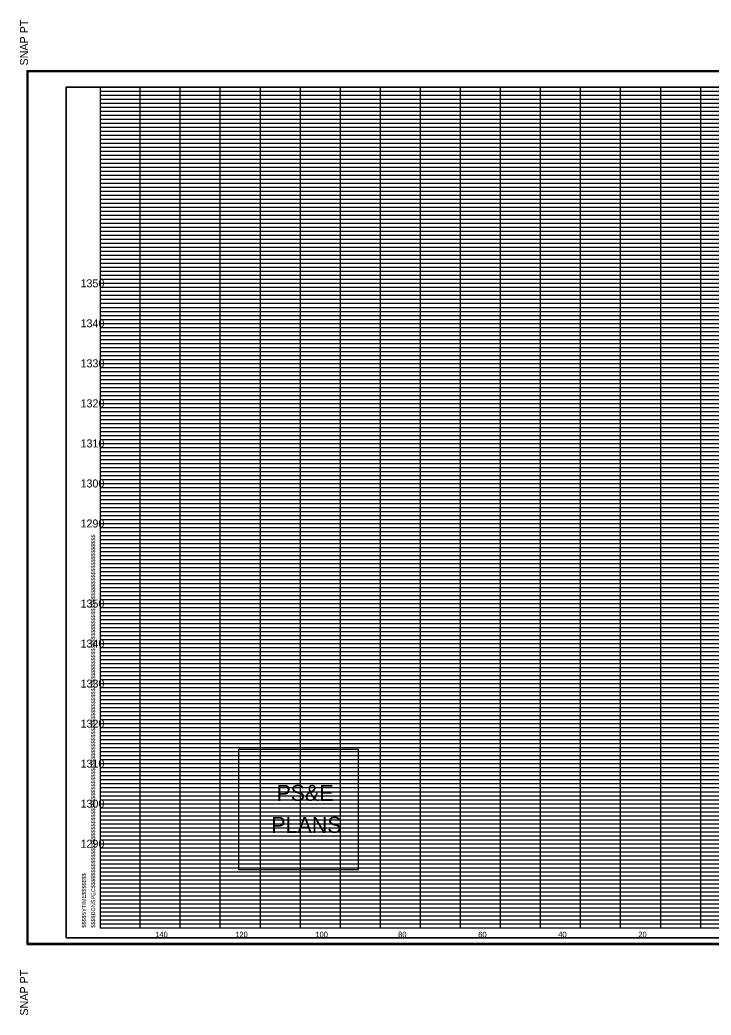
# Model space of a CAD drawing. Extents: x 980 to 1324, y 978 to 2847.
# Drawn here: x 979.9 to 1152.6, y 2058.2 to 2306.8 of the extents above; entities that cross this region are included whole.
import ezdxf

# ---------------------------------------------------------------- set-up
doc = ezdxf.new("R2010")
doc.units = 0
for name, color, linetype in [('DESIGN - SHEET - Corner Text', 7, 'Continuous'), ('DESIGN - SHEET - Light Grid', 7, 'Continuous'), ('DESIGN - SHEET - Linework', 7, 'Continuous'), ('DESIGN - SHEET - Plot Shape', 7, 'Continuous'), ('DESIGN - TYPICAL - Text', 7, 'Continuous')]:
    doc.layers.add(name, color=color, linetype=linetype)

# ---------------------------------------------------------------- blocks, each defined once
blk = doc.blocks.new('XSTSHT')
at = {"layer": 'DESIGN - SHEET - Light Grid'}
for p, q in [((0, 20.9), (8, 20.9)), ((8, 20.9), (16, 20.9)), ((0, 20.8), (8, 20.8)), ((0, 20.7), (8, 20.7)), ((8, 20.8), (16, 20.8)), ((8, 20.7), (16, 20.7)), ((0, 20.6), (8, 20.6)), ((0, 20.5), (8, 20.5)), ((0, 20.4), (8, 20.4)), ((8, 20.6), (16, 20.6)), ((8, 20.5), (16, 20.5)), ((8, 20.4), (16, 20.4)), ((0, 20.3), (8, 20.3)), ((0, 20.2), (8, 20.2)), ((8, 20.3), (16, 20.3)), ((8, 20.2), (16, 20.2)), ((0, 20.1), (8, 20.1)), ((0, 19.9), (8, 19.9)), ((8, 20.1), (16, 20.1)), ((8, 19.9), (16, 19.9)), ((0, 19.8), (8, 19.8)), ((0, 19.7), (8, 19.7)), ((8, 19.8), (16, 19.8)), ((8, 19.7), (16, 19.7)), ((0, 19.6), (8, 19.6)), ((0, 19.5), (8, 19.5)), ((0, 19.4), (8, 19.4)), ((8, 19.6), (16, 19.6)), ((8, 19.5), (16, 19.5)), ((8, 19.4), (16, 19.4)), ((0, 19.3), (8, 19.3)), ((0, 19.2), (8, 19.2)), ((8, 19.3), (16, 19.3)), ((8, 19.2), (16, 19.2)), ((0, 19.1), (8, 19.1)), ((0, 18.9), (8, 18.9)), ((8, 19.1), (16, 19.1)), ((8, 18.9), (16, 18.9)), ((0, 18.8), (8, 18.8)), ((0, 18.7), (8, 18.7)), ((8, 18.8), (16, 18.8)), ((8, 18.7), (16, 18.7)), ((0, 18.6), (8, 18.6)), ((0, 18.5), (8, 18.5)), ((0, 18.4), (8, 18.4)), ((8, 18.6), (16, 18.6)), ((8, 18.5), (16, 18.5)), ((8, 18.4), (16, 18.4)), ((0, 18.3), (8, 18.3)), ((0, 18.2), (8, 18.2)), ((8, 18.3), (16, 18.3)), ((8, 18.2), (16, 18.2)), ((0, 18.1), (8, 18.1)), ((8, 18.1), (16, 18.1)), ((0, 17.9), (8, 17.9)), ((0, 17.8), (8, 17.8)), ((0, 17.7), (8, 17.7)), ((8, 17.9), (16, 17.9)), ((8, 17.8), (16, 17.8)), ((8, 17.7), (16, 17.7)), ((0, 17.6), (8, 17.6)), ((0, 17.5), (8, 17.5)), ((8, 17.6), (16, 17.6)), ((8, 17.5), (16, 17.5)), ((0, 17.4), (8, 17.4)), ((0, 17.3), (8, 17.3)), ((0, 17.2), (8, 17.2)), ((8, 17.4), (16, 17.4)), ((8, 17.3), (16, 17.3)), ((8, 17.2), (16, 17.2)), ((0, 17.1), (8, 17.1)), ((8, 17.1), (16, 17.1)), ((0, 16.9), (8, 16.9)), ((0, 16.8), (8, 16.8)), ((0, 16.7), (8, 16.7)), ((8, 16.9), (16, 16.9)), ((8, 16.8), (16, 16.8)), ((8, 16.7), (16, 16.7)), ((0, 16.6), (8, 16.6)), ((0, 16.5), (8, 16.5)), ((8, 16.6), (16, 16.6)), ((8, 16.5), (16, 16.5)), ((0, 16.4), (8, 16.4)), ((0, 16.3), (8, 16.3)), ((0, 16.2), (8, 16.2)), ((8, 16.4), (16, 16.4)), ((8, 16.3), (16, 16.3)), ((8, 16.2), (16, 16.2)), ((0, 16.1), (8, 16.1)), ((8, 16.1), (16, 16.1)), ((0, 15.9), (8, 15.9)), ((0, 15.8), (8, 15.8)), ((0, 15.7), (8, 15.7)), ((8, 15.9), (16, 15.9)), ((8, 15.8), (16, 15.8)), ((8, 15.7), (16, 15.7)), ((0, 15.6), (8, 15.6)), ((0, 15.5), (8, 15.5)), ((8, 15.6), (16, 15.6)), ((8, 15.5), (16, 15.5)), ((0, 15.4), (8, 15.4)), ((0, 15.3), (8, 15.3)), ((0, 15.2), (8, 15.2)), ((8, 15.4), (16, 15.4)), ((8, 15.3), (16, 15.3)), ((8, 15.2), (16, 15.2)), ((0, 15.1), (8, 15.1)), ((8, 15.1), (16, 15.1)), ((0, 14.9), (8, 14.9)), ((0, 14.8), (8, 14.8)), ((0, 14.7), (8, 14.7)), ((8, 14.9), (16, 14.9)), ((8, 14.8), (16, 14.8)), ((8, 14.7), (16, 14.7)), ((0, 14.6), (8, 14.6)), ((0, 14.5), (8, 14.5)), ((8, 14.6), (16, 14.6)), ((8, 14.5), (16, 14.5)), ((0, 14.4), (8, 14.4)), ((0, 14.3), (8, 14.3)), ((0, 14.2), (8, 14.2)), ((8, 14.4), (16, 14.4)), ((8, 14.3), (16, 14.3)), ((8, 14.2), (16, 14.2)), ((0, 14.1), (8, 14.1)), ((8, 14.1), (16, 14.1)), ((0, 13.9), (8, 13.9)), ((0, 13.8), (8, 13.8)), ((0, 13.7), (8, 13.7)), ((8, 13.9), (16, 13.9)), ((8, 13.8), (16, 13.8)), ((8, 13.7), (16, 13.7)), ((0, 13.6), (8, 13.6)), ((0, 13.5), (8, 13.5)), ((8, 13.6), (16, 13.6)), ((8, 13.5), (16, 13.5)), ((0, 13.4), (8, 13.4)), ((0, 13.3), (8, 13.3)), ((0, 13.2), (8, 13.2)), ((8, 13.4), (16, 13.4)), ((8, 13.3), (16, 13.3)), ((8, 13.2), (16, 13.2)), ((0, 13.1), (8, 13.1)), ((8, 13.1), (16, 13.1)), ((0, 12.9), (8, 12.9)), ((0, 12.8), (8, 12.8)), ((0, 12.7), (8, 12.7)), ((8, 12.9), (16, 12.9)), ((8, 12.8), (16, 12.8)), ((8, 12.7), (16, 12.7)), ((0, 12.6), (8, 12.6)), ((0, 12.5), (8, 12.5)), ((8, 12.6), (16, 12.6)), ((8, 12.5), (16, 12.5)), ((0, 12.4), (8, 12.4)), ((0, 12.3), (8, 12.3)), ((0, 12.2), (8, 12.2)), ((8, 12.4), (16, 12.4)), ((8, 12.3), (16, 12.3)), ((8, 12.2), (16, 12.2)), ((0, 12.1), (8, 12.1)), ((8, 12.1), (16, 12.1)), ((0, 11.9), (8, 11.9)), ((0, 11.8), (8, 11.8)), ((0, 11.7), (8, 11.7)), ((8, 11.9), (16, 11.9)), ((8, 11.8), (16, 11.8)), ((8, 11.7), (16, 11.7)), ((0, 11.6), (8, 11.6)), ((0, 11.5), (8, 11.5)), ((8, 11.6), (16, 11.6)), ((8, 11.5), (16, 11.5)), ((0, 11.4), (8, 11.4)), ((0, 11.3), (8, 11.3)), ((0, 11.2), (8, 11.2)), ((8, 11.4), (16, 11.4)), ((8, 11.3), (16, 11.3)), ((8, 11.2), (16, 11.2)), ((0, 11.1), (8, 11.1)), ((8, 11.1), (16, 11.1)), ((0, 10.9), (8, 10.9)), ((0, 10.8), (8, 10.8)), ((0, 10.7), (8, 10.7)), ((8, 10.9), (16, 10.9)), ((8, 10.8), (16, 10.8)), ((8, 10.7), (16, 10.7)), ((0, 10.6), (8, 10.6)), ((0, 10.5), (8, 10.5)), ((8, 10.6), (16, 10.6)), ((8, 10.5), (16, 10.5)), ((0, 10.4), (8, 10.4)), ((0, 10.3), (8, 10.3)), ((0, 10.2), (8, 10.2)), ((8, 10.4), (16, 10.4)), ((8, 10.3), (16, 10.3)), ((8, 10.2), (16, 10.2)), ((0, 10.1), (8, 10.1)), ((8, 10.1), (16, 10.1)), ((0, 9.9), (8, 9.9)), ((0, 9.8), (8, 9.8)), ((0, 9.7), (8, 9.7)), ((8, 9.9), (16, 9.9)), ((8, 9.8), (16, 9.8)), ((8, 9.7), (16, 9.7)), ((0, 9.6), (8, 9.6)), ((0, 9.5), (8, 9.5)), ((8, 9.6), (16, 9.6)), ((8, 9.5), (16, 9.5)), ((0, 9.4), (8, 9.4)), ((0, 9.3), (8, 9.3)), ((0, 9.2), (8, 9.2)), ((8, 9.4), (16, 9.4)), ((8, 9.3), (16, 9.3)), ((8, 9.2), (16, 9.2)), ((0, 9.1), (8, 9.1)), ((8, 9.1), (16, 9.1)), ((0, 8.9), (8, 8.9)), ((0, 8.8), (8, 8.8)), ((8, 8.9), (16, 8.9)), ((8, 8.8), (16, 8.8)), ((0, 8.7), (8, 8.7)), ((0, 8.6), (8, 8.6)), ((0, 8.5), (8, 8.5)), ((8, 8.7), (16, 8.7)), ((8, 8.6), (16, 8.6)), ((8, 8.5), (16, 8.5)), ((0, 8.4), (8, 8.4)), ((0, 8.3), (8, 8.3)), ((8, 8.4), (16, 8.4)), ((8, 8.3), (16, 8.3)), ((0, 8.2), (8, 8.2)), ((0, 8.1), (8, 8.1)), ((8, 8.2), (16, 8.2)), ((8, 8.1), (16, 8.1)), ((0, 7.9), (8, 7.9)), ((0, 7.8), (8, 7.8)), ((8, 7.9), (16, 7.9)), ((8, 7.8), (16, 7.8)), ((0, 7.7), (8, 7.7)), ((0, 7.6), (8, 7.6)), ((0, 7.5), (8, 7.5)), ((8, 7.7), (16, 7.7)), ((8, 7.6), (16, 7.6)), ((8, 7.5), (16, 7.5)), ((0, 7.4), (8, 7.4)), ((0, 7.3), (8, 7.3)), ((8, 7.4), (16, 7.4)), ((8, 7.3), (16, 7.3)), ((0, 7.2), (8, 7.2)), ((0, 7.1), (8, 7.1)), ((8, 7.2), (16, 7.2)), ((8, 7.1), (16, 7.1)), ((0, 6.9), (8, 6.9)), ((0, 6.8), (8, 6.8)), ((8, 6.9), (16, 6.9)), ((8, 6.8), (16, 6.8)), ((0, 6.7), (8, 6.7)), ((0, 6.6), (8, 6.6)), ((0, 6.5), (8, 6.5)), ((8, 6.7), (16, 6.7)), ((8, 6.6), (16, 6.6)), ((8, 6.5), (16, 6.5)), ((0, 6.4), (8, 6.4)), ((0, 6.3), (8, 6.3)), ((8, 6.4), (16, 6.4)), ((8, 6.3), (16, 6.3)), ((0, 6.2), (8, 6.2)), ((0, 6.1), (8, 6.1)), ((8, 6.2), (16, 6.2)), ((8, 6.1), (16, 6.1)), ((0, 5.9), (8, 5.9)), ((0, 5.8), (8, 5.8)), ((8, 5.9), (16, 5.9)), ((8, 5.8), (16, 5.8)), ((0, 5.7), (8, 5.7)), ((0, 5.6), (8, 5.6)), ((0, 5.5), (8, 5.5)), ((8, 5.7), (16, 5.7)), ((8, 5.6), (16, 5.6)), ((8, 5.5), (16, 5.5)), ((0, 5.4), (8, 5.4)), ((0, 5.3), (8, 5.3)), ((8, 5.4), (16, 5.4)), ((8, 5.3), (16, 5.3)), ((0, 5.2), (8, 5.2)), ((0, 5.1), (8, 5.1)), ((8, 5.2), (16, 5.2)), ((8, 5.1), (16, 5.1)), ((0, 4.9), (8, 4.9)), ((0, 4.8), (8, 4.8)), ((8, 4.9), (16, 4.9)), ((8, 4.8), (16, 4.8)), ((0, 4.7), (8, 4.7)), ((0, 4.6), (8, 4.6)), ((0, 4.5), (8, 4.5)), ((8, 4.7), (16, 4.7)), ((8, 4.6), (16, 4.6)), ((8, 4.5), (16, 4.5)), ((0, 4.4), (8, 4.4)), ((0, 4.3), (8, 4.3)), ((8, 4.4), (16, 4.4)), ((8, 4.3), (16, 4.3)), ((0, 4.2), (8, 4.2)), ((0, 4.1), (8, 4.1)), ((8, 4.2), (16, 4.2)), ((8, 4.1), (16, 4.1)), ((0, 3.9), (8, 3.9)), ((0, 3.8), (8, 3.8)), ((8, 3.9), (16, 3.9)), ((8, 3.8), (16, 3.8)), ((0, 3.7), (8, 3.7)), ((0, 3.6), (8, 3.6)), ((0, 3.5), (8, 3.5)), ((8, 3.7), (16, 3.7)), ((8, 3.6), (16, 3.6)), ((8, 3.5), (16, 3.5)), ((0, 3.4), (8, 3.4)), ((0, 3.3), (8, 3.3)), ((8, 3.4), (16, 3.4)), ((8, 3.3), (16, 3.3)), ((0, 3.2), (8, 3.2)), ((0, 3.1), (8, 3.1)), ((8, 3.2), (16, 3.2)), ((8, 3.1), (16, 3.1)), ((0, 2.9), (8, 2.9)), ((0, 2.8), (8, 2.8)), ((8, 2.9), (16, 2.9)), ((8, 2.8), (16, 2.8)), ((0, 2.7), (8, 2.7)), ((0, 2.6), (8, 2.6)), ((0, 2.5), (8, 2.5)), ((8, 2.7), (16, 2.7)), ((8, 2.6), (16, 2.6)), ((8, 2.5), (16, 2.5)), ((0, 2.4), (8, 2.4)), ((0, 2.3), (8, 2.3)), ((8, 2.4), (16, 2.4)), ((8, 2.3), (16, 2.3)), ((0, 2.2), (8, 2.2)), ((0, 2.1), (8, 2.1)), ((8, 2.2), (16, 2.2)), ((8, 2.1), (16, 2.1)), ((0, 1.9), (8, 1.9)), ((0, 1.8), (8, 1.8)), ((8, 1.9), (16, 1.9)), ((8, 1.8), (16, 1.8)), ((0, 1.7), (8, 1.7)), ((0, 1.6), (8, 1.6)), ((0, 1.5), (8, 1.5)), ((8, 1.7), (16, 1.7)), ((8, 1.6), (16, 1.6)), ((8, 1.5), (16, 1.5)), ((0, 1.4), (8, 1.4)), ((0, 1.3), (8, 1.3)), ((8, 1.4), (16, 1.4)), ((8, 1.3), (16, 1.3)), ((0, 1.2), (8, 1.2)), ((0, 1.1), (8, 1.1)), ((8, 1.2), (16, 1.2)), ((8, 1.1), (16, 1.1)), ((0, 0.9), (8, 0.9)), ((0, 0.8), (8, 0.8)), ((8, 0.9), (16, 0.9)), ((8, 0.8), (16, 0.8)), ((0, 0.7), (8, 0.7)), ((0, 0.6), (8, 0.6)), ((0, 0.5), (8, 0.5)), ((8, 0.7), (16, 0.7)), ((8, 0.6), (16, 0.6)), ((8, 0.5), (16, 0.5)), ((0, 0.4), (8, 0.4)), ((0, 0.3), (8, 0.3)), ((8, 0.4), (16, 0.4)), ((8, 0.3), (16, 0.3)), ((0, 0.2), (8, 0.2)), ((0, 0.1), (8, 0.1)), ((8, 0.2), (16, 0.2)), ((8, 0.1), (16, 0.1))]:
    blk.add_line(p, q, dxfattribs=at)
at = {"layer": 'DESIGN - SHEET - Linework'}
for p, q in [((-1.823, -0.414), (-1.823, 21.414)), ((-1.823, 21.414), (32.217, 21.414)), ((1, 0), (1, 21)), ((2, 0), (2, 21)), ((3, 0), (3, 21)), ((4, 0), (4, 21)), ((5, 0), (5, 21)), ((6, 0), (6, 21)), ((7, 0), (7, 21)), ((8, 0), (8, 21)), ((9, 0), (9, 21)), ((10, 0), (10, 21)), ((11, 0), (11, 21)), ((12, 0), (12, 21)), ((13, 0), (13, 21)), ((14, 0), (14, 21)), ((15, 0), (15, 21)), ((0, 20), (28, 20)), ((0, 19), (32, 19)), ((0, 18), (32, 18)), ((0, 17), (32, 17)), ((0, 16), (32, 16)), ((0, 15), (32, 15)), ((0, 14), (32, 14)), ((0, 13), (32, 13)), ((0, 12), (32, 12)), ((0, 11), (32, 11)), ((0, 10), (32, 10)), ((0, 9), (32, 9)), ((0, 8), (32, 8)), ((0, 7), (32, 7)), ((0, 6), (32, 6)), ((0, 5), (32, 5)), ((0, 4), (32, 4)), ((0, 3), (32, 3)), ((0, 2), (32, 2)), ((0, 1), (32, 1)), ((-1.823, -0.414), (32.217, -0.414))]:
    blk.add_line(p, q, dxfattribs=at)
blk.add_lwpolyline([(0, 21), (0, 0), (32, 0), (32, 21), (0, 21)], dxfattribs=at)
at = {"layer": 'DESIGN - SHEET - Plot Shape'}
for points in [[(-1.803, 21.394), (32.197, 21.394), (32.197, -0.394), (-1.803, -0.394)], [(-0.85, 21), (32, 21), (32, -0.25), (-0.85, -0.25)]]:
    blk.add_lwpolyline(points, close=True, dxfattribs=at)
at = {"layer": 'DESIGN - SHEET - Corner Text'}
for s, height, p in [('  SNAP PT', 0.2, (-1.803, 21.394)), ('$$$$DGNSPEC$$$$$$$$$$$$$$$$$$$$$$$$$$$$$$$$$$$$$$$$$$$$$$$$$$$$$$$$$$$$$$$$$$$$$$$$$$$$$$$$$$$$$$$$$$$$$$$$$$$$$$$$$$$$$$$$$$$', 0.100002, (-0.126, 0)), ('$$$$SYTIME$$$$$$$', 0.1, (-0.358, 0)), ('SNAP PT  ', 0.2, (-1.803, -2.194))]:
    blk.add_text(s, height=height, rotation=90, dxfattribs=at).set_placement(p)

msp = doc.modelspace()

# ---------------------------------------------------------------- linework, layer by layer
at = {"layer": 'DESIGN - SHEET - Corner Text'}
msp.add_lwpolyline([(1034.51, 2124.53), (1034.51, 2094.53), (1064.51, 2094.53), (1064.51, 2124.53)], close=True, dxfattribs=at)
at = {"layer": 'DESIGN - SHEET - Plot Shape'}
msp.add_lwpolyline([(991.5, 2077.5), (1320, 2077.5), (1320, 2290), (991.5, 2290)], close=True, dxfattribs=at)

# ---------------------------------------------------------------- block references
at = {"layer": 'DESIGN - SHEET - Plot Shape', "xscale": 10, "yscale": 10}
msp.add_blockref('XSTSHT', (1000, 2080), dxfattribs=at)

# ---------------------------------------------------------------- texts
at = {"layer": 'DESIGN - SHEET - Corner Text'}
for s, p in [('PS&E', (1044.02, 2111.7)), ('PLANS', (1042.74, 2103.7))]:
    msp.add_text(s, height=4, dxfattribs=at).set_placement(p)
at = {"layer": 'DESIGN - TYPICAL - Text'}
for s, height, p in [('     1350     ', 2, (991.37, 2240)), ('     1340     ', 2, (991.37, 2230)), ('     1330     ', 2, (991.37, 2220)), ('     1320     ', 2, (991.37, 2210)), ('     1310     ', 2, (991.37, 2200)), ('     1300     ', 2, (991.37, 2190)), ('     1290     ', 2, (991.37, 2180)), ('     1350     ', 2, (991.37, 2160)), ('     1340     ', 2, (991.37, 2150)), ('     1330     ', 2, (991.37, 2140)), ('     1320     ', 2, (991.37, 2130)), ('     1310     ', 2, (991.37, 2120)), ('     1300     ', 2, (991.37, 2110)), ('     1290     ', 2, (991.37, 2100)), ('     140     ', 1.4, (1011.14, 2077.6)), ('     120     ', 1.4, (1031.14, 2077.6)), ('     100     ', 1.4, (1051.14, 2077.6)), ('     80     ', 1.4, (1071.82, 2077.6)), ('     60     ', 1.4, (1091.82, 2077.6)), ('     40     ', 1.4, (1111.82, 2077.6)), ('     20     ', 1.4, (1131.82, 2077.6))]:
    msp.add_text(s, height=height, dxfattribs=at).set_placement(p)

doc.saveas('drawing.dxf')
